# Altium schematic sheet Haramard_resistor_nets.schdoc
size 420 x 297 mm; Symbol: Drawing-Symbol_A4; @Project Name: Inverted_MAML_6x6; @Page Count: 3; @Update Date: 2026-07-19; @Create Date: 2026-07-19; @Schematic Name: Inverted_MAML; @Page No: 0; @Page Name: P1; Company: EasyEDA.com; Version: V1.0; Page Size: A4; Device: Drawing-Symbol_A4; @Create Time: 18:20:58; @Update Time: 18:20:58; Border: 1; Width: 1655; Height: 1170; Region Start: 1; X Region Count: 6; Y Region Count: 4; Blade Width: 10; Title Block Position: 3; @Board Name: Analog_Matrix
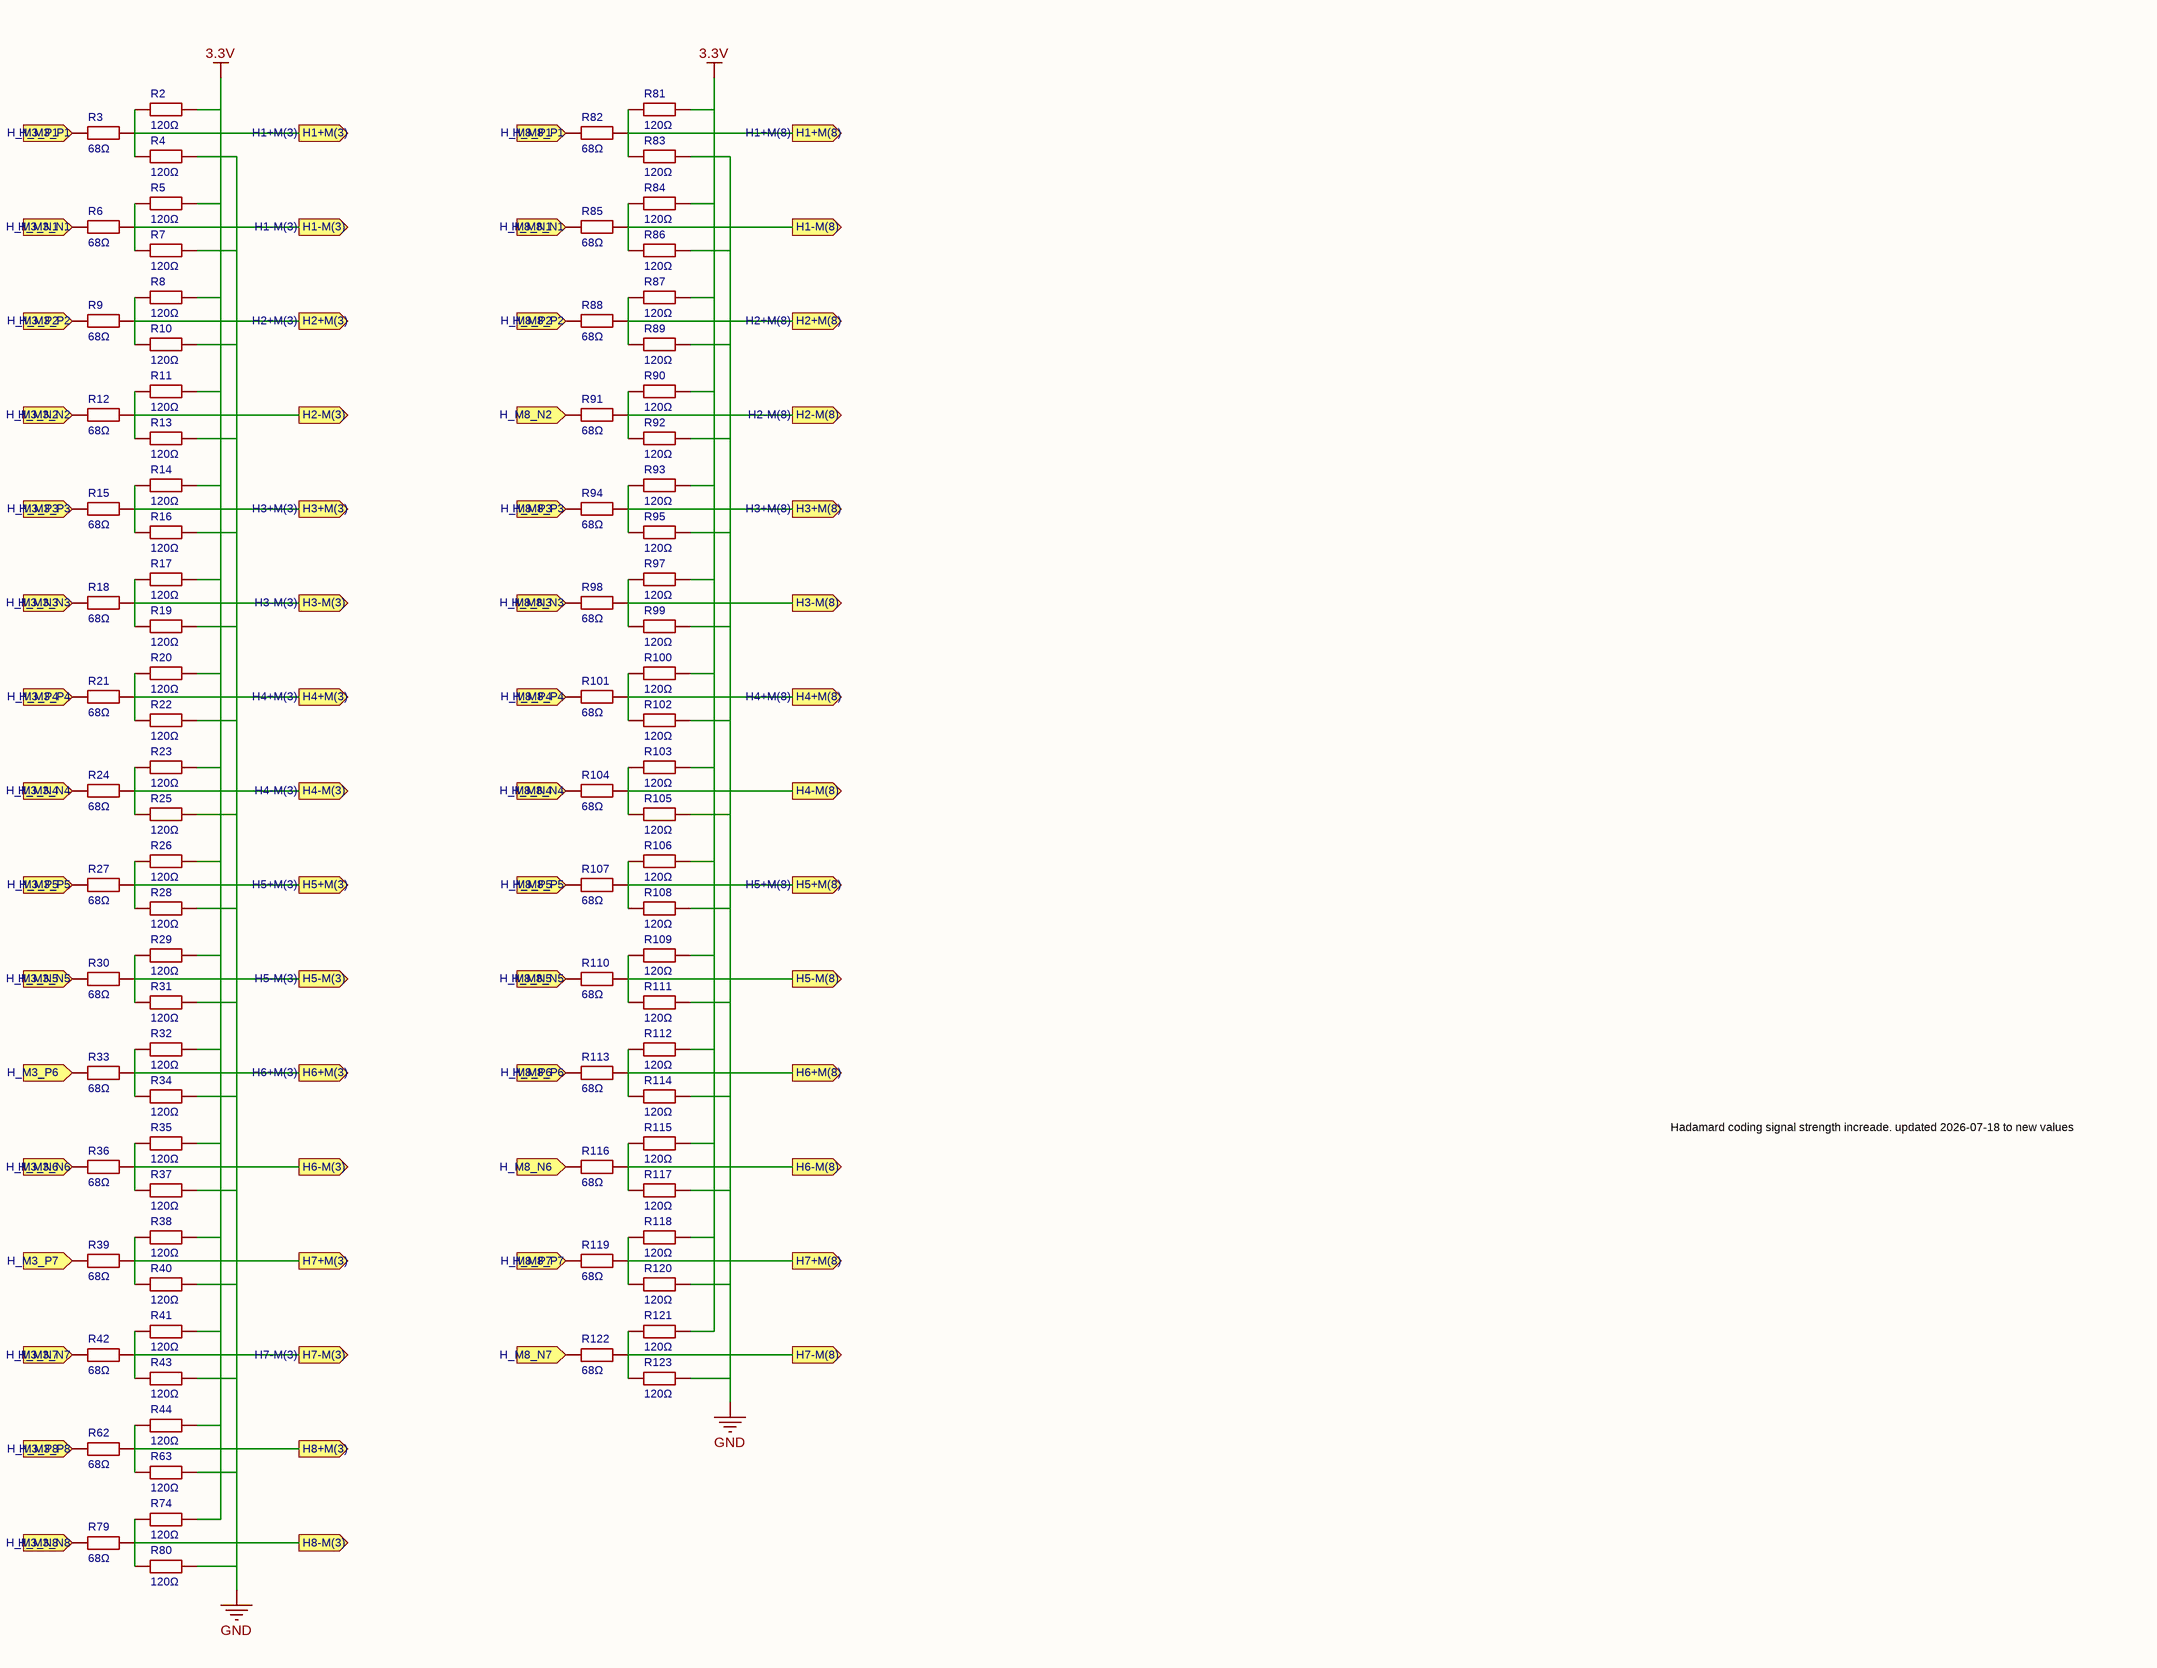
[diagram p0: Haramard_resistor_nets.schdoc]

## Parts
R2  120Ω  [R0402]
R3  68Ω  [R0402]
R4  120Ω  [R0402]
R5  120Ω  [R0402]
R6  68Ω  [R0402]
R7  120Ω  [R0402]
R8  120Ω  [R0402]
R9  68Ω  [R0402]
R10  120Ω  [R0402]
R11  120Ω  [R0402]
R12  68Ω  [R0402]
R13  120Ω  [R0402]
R14  120Ω  [R0402]
R15  68Ω  [R0402]
R16  120Ω  [R0402]
R17  120Ω  [R0402]
R18  68Ω  [R0402]
R19  120Ω  [R0402]
R20  120Ω  [R0402]
R21  68Ω  [R0402]
R22  120Ω  [R0402]
R23  120Ω  [R0402]
R24  68Ω  [R0402]
R25  120Ω  [R0402]
R26  120Ω  [R0402]
R27  68Ω  [R0402]
R28  120Ω  [R0402]
R29  120Ω  [R0402]
R30  68Ω  [R0402]
R31  120Ω  [R0402]
R32  120Ω  [R0402]
R33  68Ω  [R0402]
R34  120Ω  [R0402]
R35  120Ω  [R0402]
R36  68Ω  [R0402]
R37  120Ω  [R0402]
R38  120Ω  [R0402]
R39  68Ω  [R0402]
R40  120Ω  [R0402]
R41  120Ω  [R0402]
R42  68Ω  [R0402]
R43  120Ω  [R0402]
R44  120Ω  [R0402]
R62  68Ω  [R0402]
R63  120Ω  [R0402]
R74  120Ω  [R0402]
R79  68Ω  [R0402]
R80  120Ω  [R0402]
R81  120Ω  [R0402]
R82  68Ω  [R0402]
R83  120Ω  [R0402]
R84  120Ω  [R0402]
R85  68Ω  [R0402]
R86  120Ω  [R0402]
R87  120Ω  [R0402]
R88  68Ω  [R0402]
R89  120Ω  [R0402]
R90  120Ω  [R0402]
R91  68Ω  [R0402]
R92  120Ω  [R0402]
R93  120Ω  [R0402]
R94  68Ω  [R0402]
R95  120Ω  [R0402]
R97  120Ω  [R0402]
R98  68Ω  [R0402]
R99  120Ω  [R0402]
R100  120Ω  [R0402]
R101  68Ω  [R0402]
R102  120Ω  [R0402]
R103  120Ω  [R0402]
R104  68Ω  [R0402]
R105  120Ω  [R0402]
R106  120Ω  [R0402]
R107  68Ω  [R0402]
R108  120Ω  [R0402]
R109  120Ω  [R0402]
R110  68Ω  [R0402]
R111  120Ω  [R0402]
R112  120Ω  [R0402]
R113  68Ω  [R0402]
R114  120Ω  [R0402]
R115  120Ω  [R0402]
R116  68Ω  [R0402]
R117  120Ω  [R0402]
R118  120Ω  [R0402]
R119  68Ω  [R0402]
R120  120Ω  [R0402]
R121  120Ω  [R0402]
R122  68Ω  [R0402]
R123  120Ω  [R0402]

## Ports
H1+M(3) (out), H1+M(8) (out), H1-M(3) (out), H1-M(8) (out), H2+M(3) (out), H2+M(8) (out), H2-M(3) (out), H2-M(8) (out), H3+M(3) (out), H3+M(8) (out), H3-M(3) (out), H3-M(8) (out), H4+M(3) (out), H4+M(8) (out), H4-M(3) (out), H4-M(8) (out), H5+M(3) (out), H5+M(8) (out), H5-M(3) (out), H5-M(8) (out), H6+M(3) (out), H6+M(8) (out), H6-M(3) (out), H6-M(8) (out), H7+M(3) (out), H7+M(8) (out), H7-M(3) (out), H7-M(8) (out), H8+M(3) (out), H8-M(3) (out), H_M3_N1 (in), H_M3_N2 (in), H_M3_N3 (in), H_M3_N4 (in), H_M3_N5 (in), H_M3_N6 (in), H_M3_N7 (in), H_M3_N8 (in), H_M3_P1 (in), H_M3_P2 (in), H_M3_P3 (in), H_M3_P4 (in), H_M3_P5 (in), H_M3_P6 (in), H_M3_P7 (in), H_M3_P8 (in), H_M8_N1 (in), H_M8_N2 (in), H_M8_N3 (in), H_M8_N4 (in), H_M8_N5 (in), H_M8_N6 (in), H_M8_N7 (in), H_M8_P1 (in), H_M8_P2 (in), H_M8_P3 (in), H_M8_P4 (in), H_M8_P5 (in), H_M8_P6 (in), H_M8_P7 (in)

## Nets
3.3V: R2.1 R5.1 R8.1 R11.1 R14.1 R17.1 R20.1 R23.1 R26.1 R29.1 R32.1 R35.1 R38.1 R41.1 R44.1 R74.1 R81.1 R84.1 R87.1 R90.1 R93.1 R97.1 R100.1 R103.1 R106.1 R109.1 R112.1 R115.1 R118.1 R121.1
GND: R4.1 R7.1 R10.1 R13.1 R16.1 R19.1 R22.1 R25.1 R28.1 R31.1 R34.1 R37.1 R40.1 R43.1 R63.1 R80.1 R83.1 R86.1 R89.1 R92.1 R95.1 R99.1 R102.1 R105.1 R108.1 R111.1 R114.1 R117.1 R120.1 R123.1
H1+M(3): R2.2 R3.2 R4.2 ; port H1+M(3)
H1+M(8): R81.2 R82.2 R83.2 ; port H1+M(8)
H1-M(3): R5.2 R6.2 R7.2 ; port H1-M(3)
H1-M(8): R84.2 R85.2 R86.2 ; port H1-M(8)
H2+M(3): R8.2 R9.2 R10.2 ; port H2+M(3)
H2+M(8): R87.2 R88.2 R89.2 ; port H2+M(8)
H2-M(3): R11.2 R12.2 R13.2 ; port H2-M(3)
H2-M(8): R90.2 R91.2 R92.2 ; port H2-M(8)
H3+M(3): R14.2 R15.2 R16.2 ; port H3+M(3)
H3+M(8): R93.2 R94.2 R95.2 ; port H3+M(8)
H3-M(3): R17.2 R18.2 R19.2 ; port H3-M(3)
H3-M(8): R97.2 R98.2 R99.2 ; port H3-M(8)
H4+M(3): R20.2 R21.2 R22.2 ; port H4+M(3)
H4+M(8): R100.2 R101.2 R102.2 ; port H4+M(8)
H4-M(3): R23.2 R24.2 R25.2 ; port H4-M(3)
H4-M(8): R103.2 R104.2 R105.2 ; port H4-M(8)
H5+M(3): R26.2 R27.2 R28.2 ; port H5+M(3)
H5+M(8): R106.2 R107.2 R108.2 ; port H5+M(8)
H5-M(3): R29.2 R30.2 R31.2 ; port H5-M(3)
H5-M(8): R109.2 R110.2 R111.2 ; port H5-M(8)
H6+M(3): R32.2 R33.2 R34.2 ; port H6+M(3)
H6+M(8): R112.2 R113.2 R114.2 ; port H6+M(8)
H6-M(3): R35.2 R36.2 R37.2 ; port H6-M(3)
H6-M(8): R115.2 R116.2 R117.2 ; port H6-M(8)
H7+M(3): R38.2 R39.2 R40.2 ; port H7+M(3)
H7+M(8): R118.2 R119.2 R120.2 ; port H7+M(8)
H7-M(3): R41.2 R42.2 R43.2 ; port H7-M(3)
H7-M(8): R121.2 R122.2 R123.2 ; port H7-M(8)
H8+M(3): R44.2 R62.2 R63.2 ; port H8+M(3)
H8-M(3): R74.2 R79.2 R80.2 ; port H8-M(3)
H_M3_N1: R6.1 ; port H_M3_N1
H_M3_N2: R12.1 ; port H_M3_N2
H_M3_N3: R18.1 ; port H_M3_N3
H_M3_N4: R24.1 ; port H_M3_N4
H_M3_N5: R30.1 ; port H_M3_N5
H_M3_N6: R36.1 ; port H_M3_N6
H_M3_N7: R42.1 ; port H_M3_N7
H_M3_N8: R79.1 ; port H_M3_N8
H_M3_P1: R3.1 ; port H_M3_P1
H_M3_P2: R9.1 ; port H_M3_P2
H_M3_P3: R15.1 ; port H_M3_P3
H_M3_P4: R21.1 ; port H_M3_P4
H_M3_P5: R27.1 ; port H_M3_P5
H_M3_P6: R33.1 ; port H_M3_P6
H_M3_P7: R39.1 ; port H_M3_P7
H_M3_P8: R62.1 ; port H_M3_P8
H_M8_N1: R85.1 ; port H_M8_N1
H_M8_N2: R91.1 ; port H_M8_N2
H_M8_N3: R98.1 ; port H_M8_N3
H_M8_N4: R104.1 ; port H_M8_N4
H_M8_N5: R110.1 ; port H_M8_N5
H_M8_N6: R116.1 ; port H_M8_N6
H_M8_N7: R122.1 ; port H_M8_N7
H_M8_P1: R82.1 ; port H_M8_P1
H_M8_P2: R88.1 ; port H_M8_P2
H_M8_P3: R94.1 ; port H_M8_P3
H_M8_P4: R101.1 ; port H_M8_P4
H_M8_P5: R107.1 ; port H_M8_P5
H_M8_P6: R113.1 ; port H_M8_P6
H_M8_P7: R119.1 ; port H_M8_P7

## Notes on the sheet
- Hadamard coding signal strength increade. updated 2026-07-18 to new values

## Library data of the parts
R2 R4 R5 R7 R8 R10 R11 R13 R14 R16 R17 R19 R20 R22 R23 R25 R26 R28 R29 R31 R32 R34 R35 R37 R38 R40 R41 R43 R44 R63 R74 R80 R81 R83 R84 R86 R87 R89 R90 R92 R93 R95 R97 R99 R100 R102 R103 R105 R106 R108 R109 R111 R112 R114 R115 R117 R118 R120 R121 R123 = 0402WGF1200TCE: Type:Thick Film Resistor Resistance:120Ω Tolerance:±1% Tolerance:±1% Power(Watts):62.5mW Voltage-Supply(Max):50V Temperature Coefficient:±100ppm/℃ Temperature Coefficient:±100ppm/℃ Operating Temperature:-55℃~+155℃ Operating Temperature:-55℃~+155℃; Manufacturer: UNI-ROYAL(厚声); AddInBom: yes; ModelId: efdecb7dae4442949d28eecaf748420f0819f05c4eef4c71ace90d822a990e87; ModelName: R0402_L1.0-W0.5-H0.4; ModelTransform: 39.37,19.685,0,0,0,0,0,0,0; Tolerance: ±1%; Power(Watts): 62.5mW; Voltage-Supply(Max): 50V
R3 R6 R9 R12 R15 R18 R21 R24 R27 R30 R33 R36 R39 R42 R62 R79 R82 R85 R88 R91 R94 R98 R101 R104 R107 R110 R113 R116 R119 R122 = 0402WGJ0680TCE: Type:Thick Film Resistors Resistance: Tolerance:±5% Tolerance:±5% Power(Watts): Overload Voltage (Max): Temperature Coefficient:±100ppm/℃ Temperature Coefficient:±100ppm/℃ Operating Temperature Range:-55℃~+155℃ Operating Temperature Range:-55℃~+155℃; Manufacturer: UNI-ROYAL(厚声); AddInBom: yes; ModelId: efdecb7dae4442949d28eecaf748420f0819f05c4eef4c71ace90d822a990e87; ModelName: R0402_L1.0-W0.5-H0.4; ModelTransform: 39.37,19.685,0,0,0,0,0,0,0; Tolerance: ±5%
